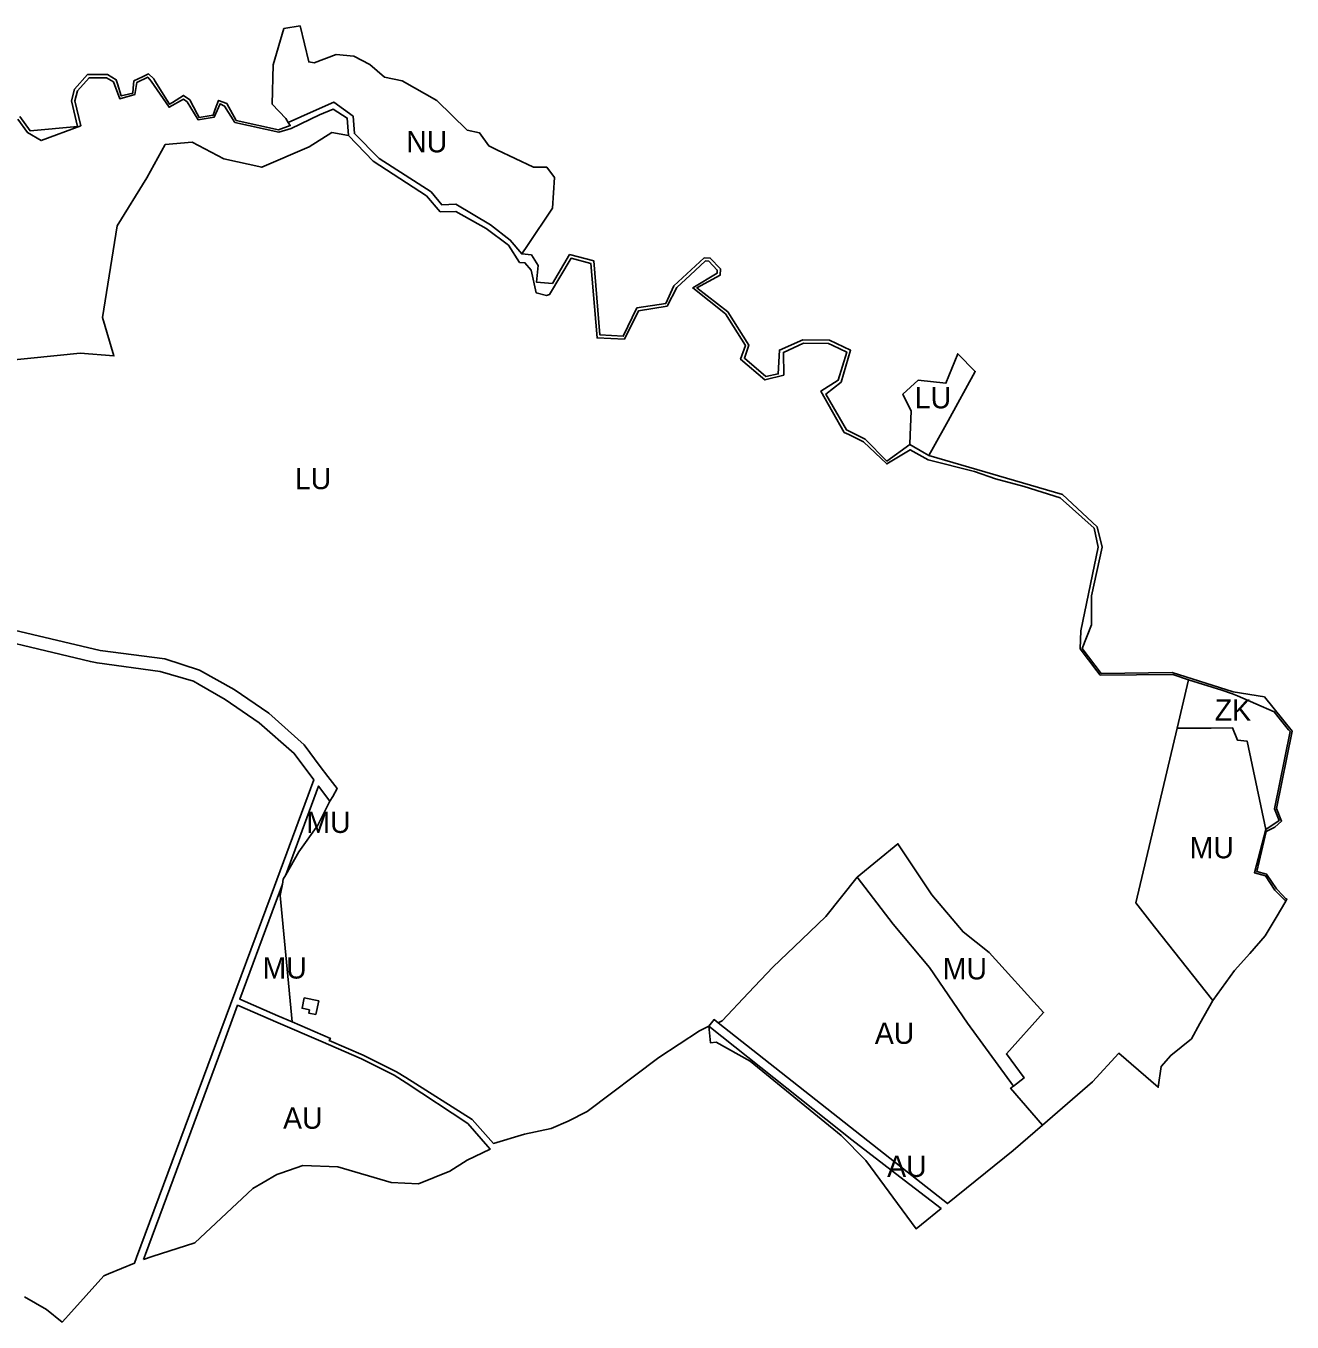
# Model space of a CAD drawing. Extents: x -522079 to -518833, y -1142398 to -1139961.
# Drawn here: x -519428 to -518833, y -1141872 to -1141262 of the extents above; entities that cross this region are included whole.
import ezdxf

# ---------------------------------------------------------------- set-up
doc = ezdxf.new("R2010")
doc.units = 0
for name, color, linetype in [('90640013', 7, 'Continuous'), ('90710013', 7, 'Continuous'), ('90730013', 7, 'Continuous'), ('90750013', 7, 'Continuous'), ('90770013', 7, 'Continuous'), ('90830013', 7, 'Continuous')]:
    doc.layers.add(name, color=color, linetype=linetype)

msp = doc.modelspace()

# ---------------------------------------------------------------- linework, layer by layer
at = {"layer": '90640013'}
msp.add_lwpolyline([(-519431.85, -1141306.14), (-519427.38, -1141312.36), (-519420.99, -1141316.12), (-519402.36, -1141309.19), (-519405.13, -1141297.52), (-519403.84, -1141292.74), (-519398.45, -1141286.57), (-519390.2, -1141286.63), (-519386.96, -1141288.54), (-519383.98, -1141296.49), (-519376.93, -1141294.5), (-519376.04, -1141288.86), (-519370.85, -1141286.3), (-519369.21, -1141288.13), (-519360.8, -1141300.45), (-519354, -1141296.72), (-519352.22, -1141297.98), (-519347.17, -1141306.35), (-519339.54, -1141305.07), (-519336.85, -1141298.85), (-519334.73, -1141299.89), (-519329.81, -1141307.56), (-519309.12, -1141312.18), (-519303.35, -1141310.46), (-519290.01, -1141304.08), (-519283.62, -1141301.34), (-519277.01, -1141305.57), (-519276.42, -1141313.78), (-519264.89, -1141325.79), (-519239.84, -1141342.13), (-519233.32, -1141349.64), (-519225.95, -1141349.55), (-519211.68, -1141357.48), (-519201.22, -1141365.24), (-519195.98, -1141373.38), (-519193.48, -1141373.59), (-519190.53, -1141377.07), (-519188.19, -1141387.74), (-519183.39, -1141388.93), (-519181.87, -1141388.46), (-519171.77, -1141371.48), (-519162.56, -1141373.86), (-519159.57, -1141408.94), (-519146.7, -1141409.56), (-519140.08, -1141396.13), (-519126.66, -1141393.95), (-519122.09, -1141385.22), (-519115.78, -1141379.37), (-519108.63, -1141372.74), (-519107.04, -1141372.83), (-519103.08, -1141377.03), (-519103.16, -1141378.52), (-519114.56, -1141385.44), (-519099.25, -1141397.67), (-519089.83, -1141412.51), (-519092.08, -1141418.96), (-519080.67, -1141428.64), (-519071.77, -1141426.39), (-519071.92, -1141415.76), (-519062.49, -1141411.31), (-519050.68, -1141411.48), (-519048.65, -1141412.42), (-519042.19, -1141415.54), (-519046.13, -1141428.81), (-519054.33, -1141433.88), (-519043.38, -1141453.33), (-519041.21, -1141454.39), (-519034.35, -1141457.76), (-519023.36, -1141468.17), (-519012.3, -1141461.46), (-519003.93, -1141466.26), (-518982.13, -1141471.67), (-518972.22, -1141475.1), (-518958.68, -1141478.71), (-518941.87, -1141484.11), (-518925.88, -1141498.42), (-518923.9, -1141507.34), (-518932.13, -1141546.59), (-518932.45, -1141555.15), (-518924.52, -1141565.49), (-518922.95, -1141567.54), (-518888.92, -1141567.21), (-518881.49, -1141569.59), (-518865.88, -1141574.59), (-518860.8, -1141576.22), (-518858.5, -1141577.22), (-518841.19, -1141584.77), (-518839.43, -1141586.95), (-518834.47, -1141593.24), (-518833.75, -1141593.98), (-518841.11, -1141630.32), (-518838.85, -1141635.75), (-518845.18, -1141639.97), (-518850.48, -1141660.34), (-518845.32, -1141661.82), (-518840.87, -1141668.48), (-518835.69, -1141673.66), (-518835.18, -1141672.79), (-518835.83, -1141672.48), (-518837.05, -1141671.02), (-518840.16, -1141667.91), (-518844.75, -1141661.05), (-518849.41, -1141659.71), (-518844.96, -1141640.98), (-518840.9, -1141638.87), (-518837.74, -1141636.08), (-518840.17, -1141630.23), (-518832.78, -1141593.74), (-518845.76, -1141577.71), (-518860.53, -1141575.36), (-518889.18, -1141566.18), (-518922.51, -1141566.63), (-518931.43, -1141555), (-518927.11, -1141543.74), (-518927.02, -1141530.23), (-518922.06, -1141507.35), (-518924.49, -1141497.8), (-518940.71, -1141482.48), (-519003.59, -1141464.2), (-519005.83, -1141462.95), (-519012.53, -1141459.04), (-519023.29, -1141466.86), (-519033.46, -1141456.53), (-519042.3, -1141452.19), (-519052, -1141435.32), (-519044.82, -1141429.69), (-519040.39, -1141414.74), (-519050.33, -1141409.98), (-519062.78, -1141409.81), (-519073.85, -1141414.66), (-519074.35, -1141425.83), (-519080.26, -1141427.02), (-519090.32, -1141418.48), (-519088.18, -1141412.32), (-519098.12, -1141396.65), (-519112.59, -1141385.36), (-519101.7, -1141379.43), (-519101.55, -1141376.47), (-519106.36, -1141371.37), (-519109.18, -1141371.2), (-519123.4, -1141384.39), (-519127.25, -1141392.73), (-519140.85, -1141394.82), (-519147.23, -1141408.12), (-519158.19, -1141407.51), (-519161.16, -1141372.68), (-519172.49, -1141369.75), (-519180.54, -1141383.29), (-519188.01, -1141382.78), (-519187.2, -1141374.82), (-519190.42, -1141369.81), (-519194.96, -1141369.43), (-519200.4, -1141362.91), (-519209.66, -1141355.81), (-519225.91, -1141346.11), (-519232.62, -1141346.31), (-519237.64, -1141340.3), (-519255.87, -1141328.5), (-519261.98, -1141324.54), (-519273.62, -1141312.83), (-519274.28, -1141304.73), (-519283.38, -1141298.07), (-519292.93, -1141302.27), (-519304.74, -1141307.68), (-519303.86, -1141309.05), (-519309.3, -1141311.02), (-519329.18, -1141306.68), (-519333.7, -1141298.67), (-519337.51, -1141297.26), (-519339.07, -1141301.4), (-519340.12, -1141304.19), (-519346.7, -1141305.23), (-519347.55, -1141303.63), (-519351.06, -1141296.96), (-519353.95, -1141294.93), (-519359.18, -1141298.18), (-519360.6, -1141299.07), (-519361.74, -1141297.24), (-519367.51, -1141288.01), (-519368.04, -1141287.17), (-519370.55, -1141284.76), (-519373.33, -1141286.11), (-519377.33, -1141288.06), (-519377.66, -1141291.53), (-519377.88, -1141293.85), (-519383.31, -1141295.11), (-519385.12, -1141289.38), (-519385.69, -1141287.55), (-519389.78, -1141285.13), (-519399.13, -1141285.07), (-519405.2, -1141292.02), (-519406.68, -1141297.5), (-519403.83, -1141309.49), (-519426.16, -1141311.48), (-519430.99, -1141304.77)], dxfattribs=at)
at = {"layer": '90710013'}
msp.add_lwpolyline([(-518845.18, -1141639.97), (-518838.85, -1141635.75), (-518841.11, -1141630.32), (-518833.75, -1141593.98), (-518834.47, -1141593.24), (-518839.43, -1141586.95), (-518841.19, -1141584.77), (-518858.5, -1141577.22), (-518860.8, -1141576.22), (-518865.88, -1141574.59), (-518881.49, -1141569.59), (-518886.88, -1141592.39), (-518870.9, -1141592.32), (-518860.72, -1141592.27), (-518858.42, -1141598.04), (-518853.84, -1141598.54), (-518845.18, -1141639.97)], dxfattribs=at)
at = {"layer": '90730013'}
for points in [[(-519304.74, -1141307.68), (-519292.93, -1141302.27), (-519283.38, -1141298.07), (-519274.28, -1141304.73), (-519273.62, -1141312.83), (-519261.98, -1141324.54), (-519255.87, -1141328.5), (-519237.64, -1141340.3), (-519232.62, -1141346.31), (-519225.91, -1141346.11), (-519209.66, -1141355.81), (-519200.4, -1141362.91), (-519194.96, -1141369.43), (-519192.3, -1141365.49), (-519180.48, -1141347.87), (-519179.55, -1141333.52), (-519183.26, -1141328.59), (-519189.49, -1141328.56), (-519206.65, -1141320.44), (-519210.53, -1141318.6), (-519214.82, -1141312.52), (-519220.59, -1141311.22), (-519234.97, -1141297.23), (-519251.16, -1141288.07), (-519259.58, -1141286.33), (-519266.36, -1141280.43), (-519273.89, -1141276.5), (-519282.24, -1141275.71), (-519292.59, -1141279.53), (-519295.1, -1141279.15), (-519299.19, -1141262.23), (-519306.82, -1141263.47), (-519311.83, -1141280.54), (-519312.28, -1141299.01), (-519305.93, -1141305.82), (-519304.74, -1141307.68)], [(-519450.75, -1141420.94), (-519402.53, -1141416.1), (-519386.73, -1141417.35), (-519392.16, -1141399.31), (-519385.2, -1141356.16), (-519371.28, -1141333.68), (-519362.63, -1141317.99), (-519350.02, -1141316.82), (-519334.98, -1141324.76), (-519317.19, -1141328.69), (-519294.89, -1141319.05), (-519284.21, -1141312.41), (-519276.42, -1141313.78), (-519277.01, -1141305.57), (-519283.62, -1141301.34), (-519290.01, -1141304.08), (-519303.35, -1141310.46), (-519309.12, -1141312.18), (-519329.81, -1141307.56), (-519334.73, -1141299.89), (-519336.85, -1141298.85), (-519339.54, -1141305.07), (-519347.17, -1141306.35), (-519352.22, -1141297.98), (-519354, -1141296.72), (-519360.8, -1141300.45), (-519369.21, -1141288.13), (-519370.85, -1141286.3), (-519376.04, -1141288.86), (-519376.93, -1141294.5), (-519383.98, -1141296.49), (-519386.96, -1141288.54), (-519390.2, -1141286.63), (-519398.45, -1141286.57), (-519403.84, -1141292.74), (-519405.13, -1141297.52), (-519402.36, -1141309.19), (-519420.99, -1141316.12), (-519427.38, -1141312.36), (-519431.85, -1141306.14)]]:
    msp.add_lwpolyline(points, dxfattribs=at)
at = {"layer": '90750013'}
msp.add_lwpolyline([(-519428.71, -1141859.77), (-519418.41, -1141865.69), (-519411.05, -1141871.62), (-519409.46, -1141869.87), (-519408.1, -1141868.36), (-519391.5, -1141849.93), (-519389.29, -1141849.01), (-519377.1, -1141843.96), (-519376.07, -1141841.19), (-519336.47, -1141734.52), (-519312.84, -1141670.86), (-519292.71, -1141616.64), (-519301.98, -1141604.24), (-519318.43, -1141589.84), (-519334.38, -1141578.92), (-519346.66, -1141571.83), (-519349.35, -1141570.28), (-519364.95, -1141565.79), (-519394.67, -1141561.74), (-519397.82, -1141561.07), (-519464.89, -1141545.09)], dxfattribs=at)
for points in [[(-519037.2, -1141662.52), (-519051.93, -1141680.89), (-519063.3, -1141691.75), (-519076.93, -1141704.76), (-519088.31, -1141716.77), (-519100.73, -1141730.04), (-519102.66, -1141730.9), (-519013.82, -1141800.95), (-518994.87, -1141815.89), (-518963.91, -1141791), (-518950.14, -1141779.05), (-518965.15, -1141761.66), (-518963.82, -1141760.65), (-518985.35, -1141731.05), (-519003.26, -1141704.92), (-519020.32, -1141684.47)], [(-519372.86, -1141842.19), (-519368.78, -1141840.86), (-519348.63, -1141834.32), (-519321.4, -1141808.82), (-519316.53, -1141805.97), (-519310.14, -1141802.21), (-519308.25, -1141801.56), (-519297.93, -1141798.04), (-519281.47, -1141798.57), (-519256.37, -1141806.05), (-519243.51, -1141806.68), (-519228.74, -1141800.67), (-519220.64, -1141795.43), (-519209.88, -1141790.38), (-519211, -1141789.08), (-519220.27, -1141778.33), (-519249.34, -1141759.14), (-519254.9, -1141755.61), (-519270.39, -1141747.88), (-519289.52, -1141739.58), (-519309.44, -1141730.94), (-519328.61, -1141722.63), (-519336.07, -1141742.78), (-519371.92, -1141839.65)], [(-519107.07, -1141732.42), (-519106.29, -1141740.33), (-519103.5, -1141739.96), (-519087.6, -1141748.94), (-519044.72, -1141783.93), (-519033.21, -1141795.69), (-519009.58, -1141827.71), (-519007.06, -1141825.69), (-518997.83, -1141818.27), (-519017.2, -1141803.32), (-519039.72, -1141785.92)]]:
    msp.add_lwpolyline(points, close=True, dxfattribs=at)
at = {"layer": '90770013'}
for points in [[(-518886.88, -1141592.39), (-518881.49, -1141569.59), (-518888.92, -1141567.21), (-518922.95, -1141567.54), (-518924.52, -1141565.49), (-518932.45, -1141555.15), (-518932.13, -1141546.59), (-518923.9, -1141507.34), (-518925.88, -1141498.42), (-518941.87, -1141484.11), (-518958.68, -1141478.71), (-518972.22, -1141475.1), (-518982.13, -1141471.67), (-519003.93, -1141466.26), (-519012.3, -1141461.46), (-519023.36, -1141468.17), (-519034.35, -1141457.76), (-519041.21, -1141454.39), (-519043.38, -1141453.33), (-519054.33, -1141433.88), (-519046.13, -1141428.81), (-519042.19, -1141415.54), (-519048.65, -1141412.42), (-519050.68, -1141411.48), (-519062.49, -1141411.31), (-519071.92, -1141415.76), (-519071.77, -1141426.39), (-519080.67, -1141428.64), (-519092.08, -1141418.96), (-519089.83, -1141412.51), (-519099.25, -1141397.67), (-519114.56, -1141385.44), (-519103.16, -1141378.52), (-519103.08, -1141377.03), (-519107.04, -1141372.83), (-519108.63, -1141372.74), (-519115.78, -1141379.37), (-519122.09, -1141385.22), (-519126.66, -1141393.95), (-519140.08, -1141396.13), (-519146.7, -1141409.56), (-519159.57, -1141408.94), (-519162.56, -1141373.86), (-519171.77, -1141371.48), (-519181.87, -1141388.46), (-519183.39, -1141388.93), (-519188.19, -1141387.74), (-519190.53, -1141377.07), (-519193.48, -1141373.59), (-519195.98, -1141373.38), (-519201.22, -1141365.24), (-519211.68, -1141357.48), (-519225.95, -1141349.55), (-519233.32, -1141349.64), (-519239.84, -1141342.13), (-519264.89, -1141325.79), (-519276.42, -1141313.78), (-519284.21, -1141312.41), (-519294.89, -1141319.05), (-519317.19, -1141328.69), (-519334.98, -1141324.76), (-519350.02, -1141316.82), (-519362.63, -1141317.99), (-519371.28, -1141333.68), (-519385.2, -1141356.16), (-519392.16, -1141399.31), (-519386.73, -1141417.35), (-519402.53, -1141416.1), (-519450.75, -1141420.94)], [(-519012.53, -1141459.04), (-519005.83, -1141462.95), (-519003.59, -1141464.2), (-519001.41, -1141460.26), (-518994.55, -1141447.83), (-518981.74, -1141424.63), (-518989.97, -1141416.33), (-518995.53, -1141430.25), (-519008.63, -1141428.83), (-519015.74, -1141435.38), (-519011.87, -1141443.33), (-519012.34, -1141454.52), (-519012.53, -1141459.04)], [(-519465.6, -1141538.79), (-519393.2, -1141555.81), (-519362.75, -1141559.82), (-519346.5, -1141565.05), (-519330.14, -1141574.2), (-519313.9, -1141585.4), (-519297.36, -1141600.15), (-519289.76, -1141610.43), (-519286.19, -1141615.06), (-519281.83, -1141620.82), (-519283.88, -1141624.46), (-519285.15, -1141626.73), (-519290.81, -1141638.01), (-519299.72, -1141650.6), (-519305.95, -1141661.39), (-519307.13, -1141663.43), (-519307.53, -1141665.67), (-519308.5, -1141671.02), (-519302.86, -1141730.53), (-519284.96, -1141738.29), (-519285.49, -1141739.31), (-519269.54, -1141746.07), (-519253.85, -1141753.9), (-519249.47, -1141756.69), (-519218.36, -1141776.45), (-519208.31, -1141787.64), (-519193.63, -1141783.33), (-519181.21, -1141780.54), (-519173.18, -1141777.23), (-519164.17, -1141772.59), (-519130.56, -1141747.22), (-519111.34, -1141734.71), (-519107.07, -1141732.42), (-519104.58, -1141729.38), (-519102.66, -1141730.9), (-519100.73, -1141730.04), (-519088.31, -1141716.77), (-519076.93, -1141704.76), (-519063.3, -1141691.75), (-519051.93, -1141680.89), (-519037.2, -1141662.52), (-519018.14, -1141646.74), (-519002.22, -1141670.75), (-518987.45, -1141688.21), (-518975.25, -1141697.8), (-518949.63, -1141726.06), (-518967.09, -1141745.55), (-518958.75, -1141756.79), (-518963.82, -1141760.65), (-518965.15, -1141761.66), (-518950.14, -1141779.05), (-518926.6, -1141758.63), (-518914.26, -1141745.22), (-518895.73, -1141761.19), (-518894.38, -1141751.49), (-518889.83, -1141746.28), (-518880.1, -1141738.42), (-518876.08, -1141731.29), (-518869.99, -1141720.5), (-518897.41, -1141685.82), (-518906.3, -1141674.57), (-518886.88, -1141592.39)], [(-519291.74, -1141727), (-519295.11, -1141726.32), (-519294.81, -1141724.84), (-519298.29, -1141724.1), (-519297.27, -1141719.22), (-519290.41, -1141720.65), (-519291.74, -1141727)]]:
    msp.add_lwpolyline(points, dxfattribs=at)
at = {"layer": '90830013'}
for points in [[(-518845.18, -1141639.97), (-518853.84, -1141598.54), (-518858.42, -1141598.04), (-518860.72, -1141592.27), (-518870.9, -1141592.32), (-518886.88, -1141592.39), (-518906.3, -1141674.57), (-518897.41, -1141685.82), (-518869.99, -1141720.5), (-518859.88, -1141706.38), (-518852.72, -1141698.29), (-518845.39, -1141690.02), (-518840.27, -1141681.38), (-518835.69, -1141673.66), (-518840.87, -1141668.48), (-518845.32, -1141661.82), (-518850.48, -1141660.34), (-518845.18, -1141639.97)], [(-519305.95, -1141661.39), (-519299.72, -1141650.6), (-519290.81, -1141638.01), (-519285.15, -1141626.73), (-519290.49, -1141619.61), (-519305.95, -1141661.39)], [(-519037.2, -1141662.52), (-519020.32, -1141684.47), (-519003.26, -1141704.92), (-518985.35, -1141731.05), (-518963.82, -1141760.65), (-518958.75, -1141756.79), (-518967.09, -1141745.55), (-518949.63, -1141726.06), (-518975.25, -1141697.8), (-518987.45, -1141688.21), (-519002.22, -1141670.75), (-519018.14, -1141646.74), (-519037.2, -1141662.52)], [(-519302.86, -1141730.53), (-519308.5, -1141671.02), (-519307.53, -1141665.67), (-519312.39, -1141678.8), (-519327.57, -1141719.82), (-519309.63, -1141727.6), (-519302.86, -1141730.53)]]:
    msp.add_lwpolyline(points, dxfattribs=at)

# ---------------------------------------------------------------- texts
at = {"layer": '90710013'}
msp.add_text('ZK', height=10, rotation=360, dxfattribs=at).set_placement((-518869.13, -1141588.84))
at = {"layer": '90730013'}
msp.add_text('NU', height=10, rotation=0, dxfattribs=at).set_placement((-519249.32, -1141321.68))
at = {"layer": '90750013'}
for p in [(-519028.97, -1141740.82), (-519307.2, -1141780.73), (-519023.17, -1141803.38)]:
    msp.add_text('AU', height=10, rotation=360, dxfattribs=at).set_placement(p)
at = {"layer": '90770013'}
for rotation, p in [(360, (-519010.17, -1141442.04)), (0, (-519301.65, -1141480.04))]:
    msp.add_text('LU', height=10, rotation=rotation, dxfattribs=at).set_placement(p)
at = {"layer": '90830013'}
for rotation, p in [(360, (-519296.22, -1141641.64)), (0, (-518880.94, -1141653.57)), (0, (-519316.87, -1141710.12)), (360, (-518997.01, -1141710.51))]:
    msp.add_text('MU', height=10, rotation=rotation, dxfattribs=at).set_placement(p)

doc.saveas('drawing.dxf')
